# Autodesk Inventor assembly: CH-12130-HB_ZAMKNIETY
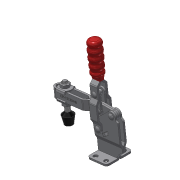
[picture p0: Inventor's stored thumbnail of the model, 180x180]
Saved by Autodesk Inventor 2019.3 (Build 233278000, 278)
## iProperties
Company: Î¢ÈíÖÐ¹ú
Created: 2012-09
Part Number: CH-12130-HB_ZAMKNIETY
Material: Ogólny
Description: STEP AP203
Document SubType Name: Assembly
Designer: CADENGINEERING4
Sending System: SolidWorks 2010
Preprocessor: SwSTEP 2.0
Title: CH-12130-HB.STEP
Author: Î¢ÈíÓÃ»§
Revision Number: ÈÎºÎ
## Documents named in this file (12)
- D:\Vault_2016\Projekty\NASZ KATALOG\CLAMPTEK\STRONA\Vertical toggle clamp\CH-12130-HB\CH-12130-HB_ZAMKNIETY.iam
- D:\Vault_2016\Projekty\NASZ KATALOG\CLAMPTEK\STEP FILES\Vertical toggle clamp\CH-12130-HB\CH-12130-HB-02 U-BAR.ipt
- D:\Vault_2016\Projekty\NASZ KATALOG\CLAMPTEK\STEP FILES\Vertical toggle clamp\CH-12130-HB\CH-12130-03 STRAIGHT HANDLE.ipt
- D:\Vault_2016\Projekty\NASZ KATALOG\CLAMPTEK\STEP FILES\Vertical toggle clamp\CH-12130-HB\CH-12130-07.ipt
- D:\Vault_2016\Projekty\NASZ KATALOG\CLAMPTEK\STEP FILES\Vertical toggle clamp\CH-12130-HB\CH-FC-56212 SPINDLE SUPPLIED.ipt
- D:\Vault_2016\Projekty\NASZ KATALOG\CLAMPTEK\STEP FILES\Vertical toggle clamp\CH-12130-HB\CH-12130-HB-01 FLANGED BASE.ipt
- D:\Vault_2016\Projekty\NASZ KATALOG\CLAMPTEK\STEP FILES\Vertical toggle clamp\CH-12130-HB\CH-12130-05.ipt
- D:\Vault_2016\Projekty\NASZ KATALOG\CLAMPTEK\STEP FILES\Vertical toggle clamp\CH-12130-HB\CH-FC-56212 Nut.ipt
- D:\Vault_2016\Projekty\NASZ KATALOG\CLAMPTEK\STEP FILES\Vertical toggle clamp\CH-12130-HB\CH-12130-08.ipt
- D:\Vault_2016\Projekty\NASZ KATALOG\CLAMPTEK\STEP FILES\Vertical toggle clamp\CH-12130-HB\CH-12130-06.ipt
- D:\Vault_2016\Projekty\NASZ KATALOG\CLAMPTEK\STEP FILES\Vertical toggle clamp\CH-12130-HB\CH-12130-04 CONNECTING-PLATE.ipt
- D:\Vault_2016\Projekty\NASZ KATALOG\CLAMPTEK\STEP FILES\Vertical toggle clamp\CH-12130-HB\CH-FW-516.ipt
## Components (15 placed, 15 different names)
1. CH-12130-HB-02 U-BAR_1
2. CH-12130-03 STRAIGHT HANDLE_2
3. CH-12130-07_3
4. CH-FC-56212 SPINDLE SUPPLIED_4
5. CH-12130-HB-01 FLANGED BASE_5
6. CH-12130-05_6
7. CH-FC-56212 Nut_7
8. CH-12130-08_8
9. CH-12130-06_9
10. CH-12130-04 CONNECTING-PLATE_10
11. CH-12130-06_11
12. CH-12130-08_12
13. CH-FW-516_13
14. CH-FW-516_14
15. CH-FC-56212 Nut_15
